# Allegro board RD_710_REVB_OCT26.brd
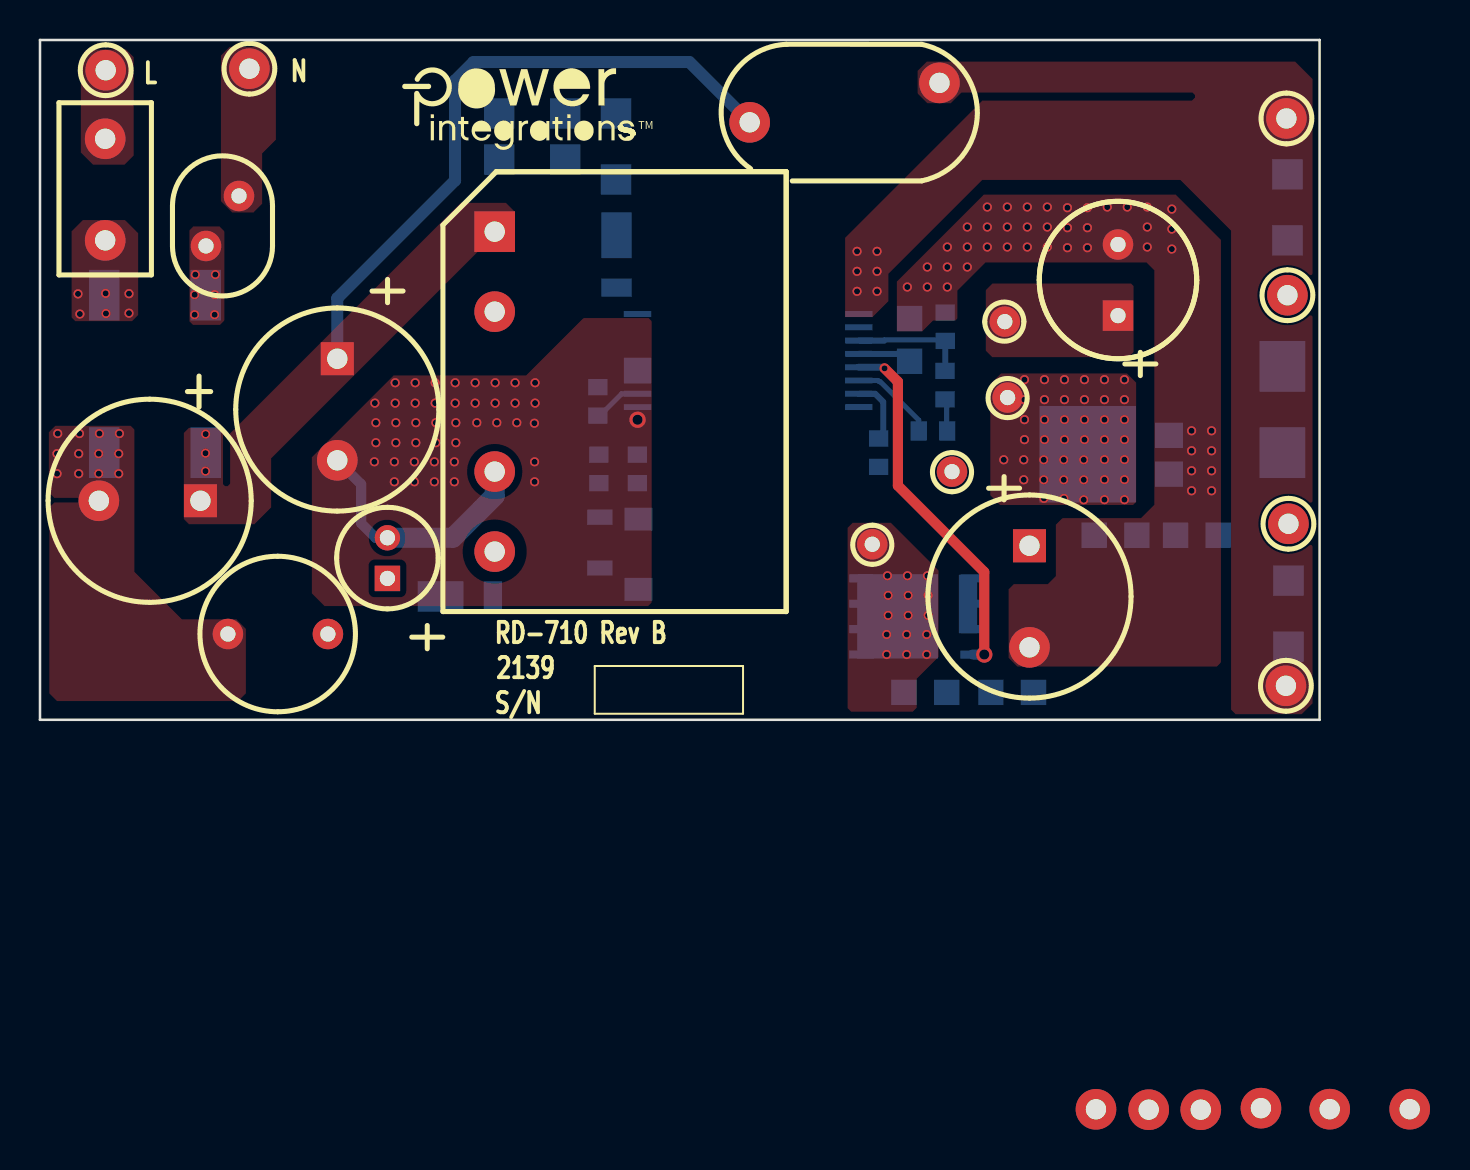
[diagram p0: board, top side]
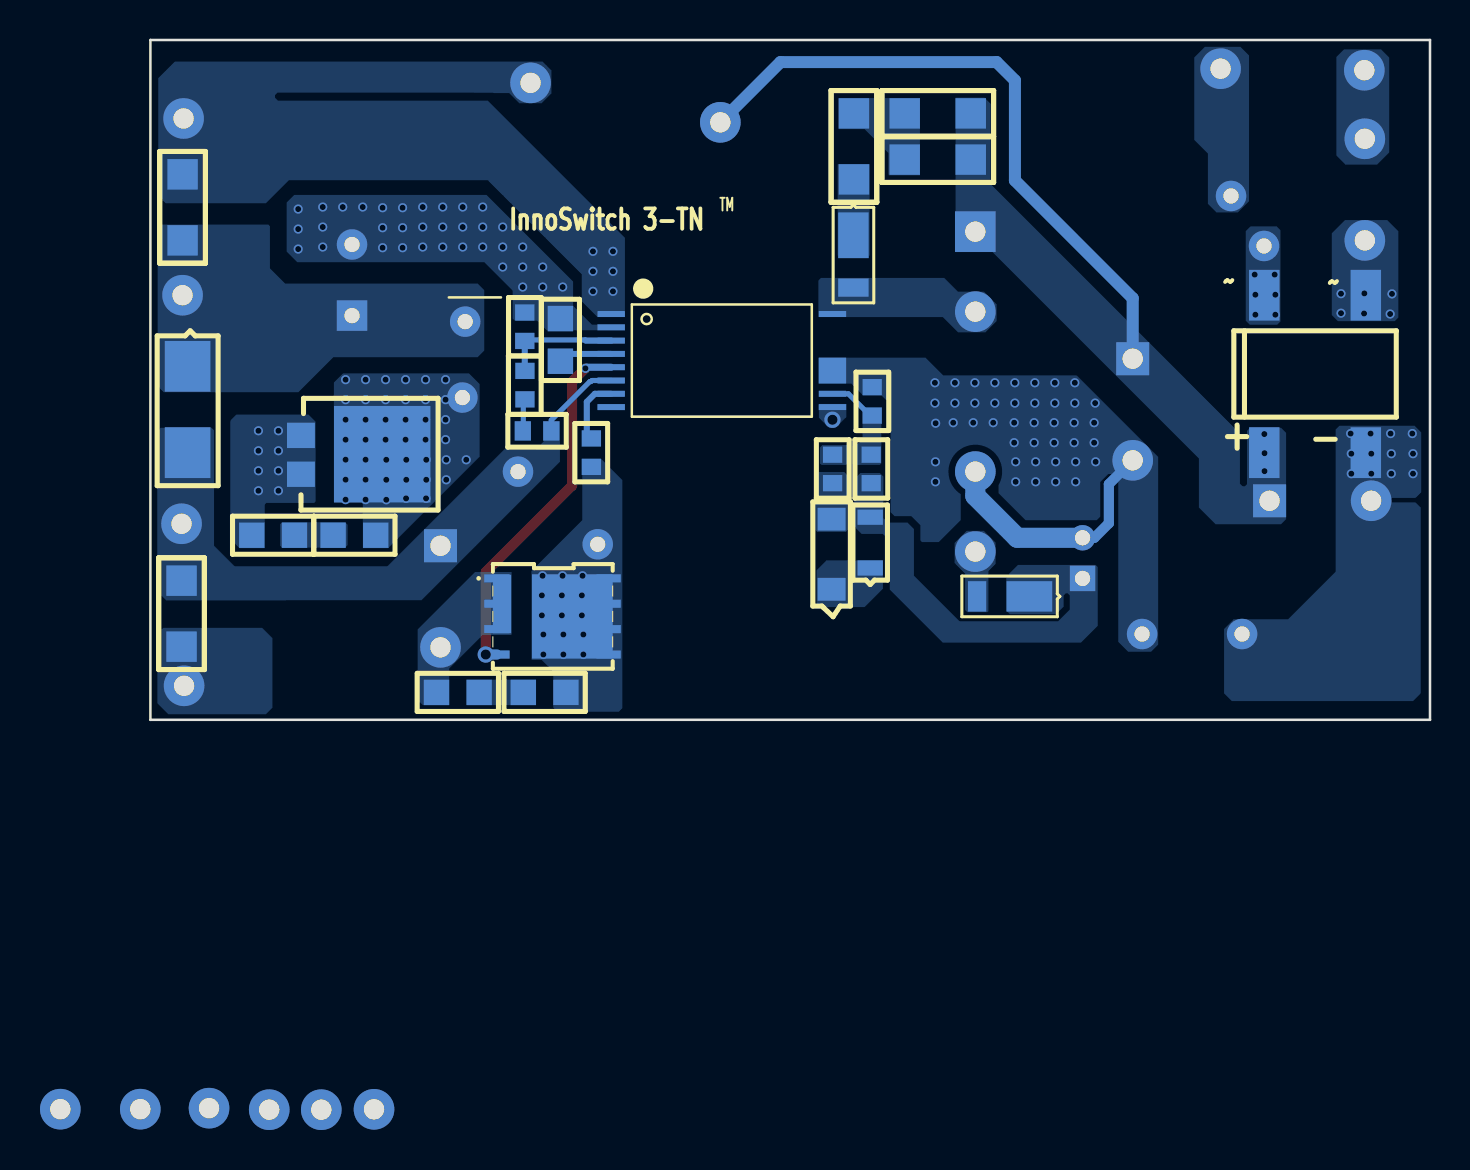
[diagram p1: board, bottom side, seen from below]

Outline 64 x 34 mm; copper layers: TOP, BOTTOM. Coordinates in mm from the lower left corner of the outline.
Outline path: 0,34 0,0 64,0 64,34 0,34

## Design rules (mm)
constraint set DEFAULT: min track width 0.508

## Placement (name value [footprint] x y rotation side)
BR1  DF08S  [PISMDDFS]  8.29 13.41 0 bottom
C1  15 uF  [PIPOLCAPCYLD400LS200040]  8.02 10.96 180 top
C2  15 uF  [PIPOLCAPCYLD400LS200040]  14.87 18.06 270 top
C3  1000 pF  [PISMC1206]  22.97 28.02 0 bottom
C4  22  uF  [PIPOLCAPCLYD200LS80030]  17.38 7.07 90 top
C5  0.47 uF  [PISMC0603]  27.9 15.21 90 bottom
C6  470 pF  [PINPCAPRAD8X5MMD030]  45.5 30.38 180 top
C7  2.2 uF  [PISMC0805]  43.49 20.07 270 bottom
C8  2.2 nF  [PISMC0805]  47.56 1.37 0 bottom
C9  1 nF  [PISMC0805]  52.73 9.23 0 bottom
C10  680 uF  [PIPOLCAPCYLD400LS200040]  49.49 8.71 270 top
C11  560 uF  [PIPOLCAPCLYD320LS140030]  53.92 20.22 90 top
C12  2.2 uF  [PISMC1206]  62.44 6.96 270 bottom
C13  2.2 uF  [PISMC1206]  62.39 23.98 90 bottom
C14  2.2 nF  [PISMC0603]  45.27 17.45 270 bottom
D1  DFLR1600-7  [PISMDDFLR120012]  28.84 24.26 90 bottom
D2  DFLR1200-7  [PISMDDFLR120012]  20.01 6.17 180 bottom
D3  BAV21WS-7-F  [PISMSOD323]  28 7.59 90 bottom
D4  V12P12-M3/86A  [PI_SM_D_TO-277A]  56.47 12.27 270 bottom
F1  1 A  [PI_RST_MICROFUSE]  3.26 29.06 270 top
FL1  Hole_30mils  [PI_HOLE_30MIL]  48.26 19.91 270 top
FL2  Hole_30mils  [PI_HOLE_30MIL]  48.4 16.12 0 top
FL3  Hole_30mils  [PI_HOLE_30MIL]  45.62 12.41 0 top
FL4  Hole_30mils  [PI_HOLE_30MIL]  41.63 8.78 0 top
L1  330 uH  [PICHOKETOKINVD345H453LS197D030]  9.4 4.29 0 top
LINE  WHT  [PITPKEYSTONE100X100]  10.47 32.56 0 top
NEUTRAL  BLK  [PITPKEYSTONE100X100]  3.29 32.49 0 top
NOREF  -  []  -227.6 -144.78 0 top
NOREF#2  -  []  64 34 270 top
NOREF#3  -  []  0 0 0 top
NOREF#4  -  []  -149.78 54.23 0 top
NOREF#5  -  []  18.2 32.38 0 top
Q1  SI7478DP-T1-E3  [PISMPQFN5X6B]  46.67 7.08 270 bottom
R1  200 k  [PISMR1206]  22.97 30.33 0 bottom
R2  68  [PISMR1206]  28.81 30.33 270 bottom
R3  36  [PISMR0603]  29.88 11.84 90 bottom
R4  12.7 k  [PISMR0603]  27.95 11.84 90 bottom
R5  47  [PISMR0603]  41.94 14.07 270 bottom
R7  62  [PISMR0805]  43.21 1.37 0 bottom
R8  30  [PISMR0805]  56.79 9.23 0 bottom
R9  100  [PISMR0603]  43.95 14.45 0 bottom
R10  3.0 Meg  [PISMR0603]  45.28 18.95 90 bottom
RT1  10  [PI_RAD_276DX197T_LS100D025]  9.13 23.7 90 top
T1  EE22  [PIBOBBINEE22V10PTDK]  22.74 24.41 0 top
U1  INN3074M  [PI_SM_MINSOP16A_1]  40.95 20.29 270 bottom
UNK5V  RED  [PITPKEYSTONE100X100]  62.44 9.8 0 top
UNK5VRTN  WHT  [PITPKEYSTONE100X100]  62.32 1.7 0 top
UNK12V  YEL  [PITPKEYSTONE100X100]  62.39 21.23 0 top
UNK12VRTN  BLK  [PITPKEYSTONE100X100]  62.34 30.07 0 top
VR1  MMSZ5234B-7-F  [PI_SM_SOD-123_12]  29.93 6.53 90 bottom
VR2  SMAZ8V2-13-F  [PISMDO214AC12]  62.14 17.68 270 bottom

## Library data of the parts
BR1 = DIODE BRIDGE_+-~~
C1 C2 = CAP POL: alternate symbols: (pipolcapclyd400x630ls200030h)
C3 C5-C9 C12-C14 = CAP NP
C4 = CAP POL: alternate symbols: (pipolcapclyd200ls80030h)
C10 = CAP POL: alternate symbols: (pipolcapclyd400x530ls200030h)
C11 = CAP POL: alternate symbols: (pipolcapclyd320ls140030430h)
D1-D3 = DIODE
D4 = DIODE SCHOTTKY_TO-277A
F1 = FUSE: alternate symbols: (pirstmicrofusehoz)
FL1-FL4 = FlyingLead
L1 = INDUCTOR
LINE UNK5V UNK5VRTN UNK12V UNK12VRTN = TESTPOINT
NEUTRAL = TESTPOINT: alternate symbols: (TP_TH_CR2_D1_1)
Q1 = FET_N_SGD_123_4_5678
R1-R5 R7-R10 = R
RT1 = THERMISTOR
T1 = BEEL22_10P/GENERIC
U1 = Inno3TNMinSOP16_0
VR1 VR2 = DIODE_ZENER

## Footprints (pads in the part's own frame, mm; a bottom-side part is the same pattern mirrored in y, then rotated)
PI_HOLE_30MIL
  round 1.524 hole 0.762: 1(0,0)
PI_RAD_276DX197T_LS100D025
  round 1.524 hole 0.762: 1(0,0.825) 2(2.5,-0.825)
PI_RST_MICROFUSE
  round 2.032 hole 1.016: 1(0,0) 2(5.08,0)
PI_SM_D_TO-277A
  rect 1.27x1.397 smd: 1(-0.015,0) 2(-1.956,0)
  rect 4.826x4.826 smd: 3(-1.016,4.064)
PI_SM_MINSOP16A_1
  rect 0.3x1.37 smd: 1(0,0) 2(0.665,0) 3(1.33,0) 4(1.995,0) 5(2.66,0) 6(3.325,0) 7(3.99,0) 8(4.655,0) 9(4.655,11.067) 10(3.99,11.067) 16(0,11.067)
  rect 1.292x1.37 smd: 11(2.829,11.067)
PI_SM_SOD-123_12
  rect 1.143x1.397 smd: 1(0,0) 2(3.505,0)
PIBOBBINEE22V10PTDK
  rect 2.032x2.032 hole 1.016: 1(0,0)
  round 2.032 hole 1.016: 2(0,-4) 3(30.074,-43.891) 4(0,-11.999) 5(0,-15.999) 6(45.764,-43.885) 7(41.764,-43.885) 8(38.325,-43.834) 9(35.315,-43.91) 10(32.711,-43.91)
PICHOKETOKINVD345H453LS197D030
  round 1.524 hole 0.762: 1(0,0) 2(5.001,0)
PINPCAPRAD8X5MMD030
  round 2.032 hole 1.016: 1(0.508,-1.473) 2(10,0.5)
PIPOLCAPCLYD200LS80030
  rect 1.27x1.27 hole 0.762: 1(0,0)
  round 1.27 hole 0.762: 2(2.032,0)
PIPOLCAPCLYD320LS140030
  rect 1.524x1.524 hole 0.762: 1(0,0)
  round 1.524 hole 0.762: 2(3.556,0)
PIPOLCAPCYLD400LS200040
  rect 1.651x1.651 hole 1.016: 1(0,0)
  round 2.032 hole 1.016: 2(5.08,0)
PISMC0603
  rect 0.813x0.965 smd: 1(0,0) 2(1.422,0)
PISMC0805
  rect 1.27x1.27 smd: 1(0,0) 2(2.134,0)
PISMC1206
  rect 1.524x1.524 smd: 1(0,0) 2(3.302,0)
PISMDDFLR120012
  rect 2.286x1.524 smd: 1(-0.025,0)
  rect 0.914x1.524 smd: 2(-2.642,0)
PISMDDFS
  rect 1.524x2.54 smd: 1(0,0.051) 2(-5.08,0.051) 3(0,-7.823) 4(-5.08,-7.823)
PISMDO214AC12
  rect 2.54x2.286 smd: 1(0,0) 2(4.318,0)
PISMPQFN5X6B
  rect 0.406x1.27 smd: 1(0,0) 2(1.27,0) 3(2.54,0) 4(3.81,0)
  rect 0.406x1.219 smd: 5(3.81,5.588) 6(2.54,5.588) 7(1.27,5.588) 8(0,5.588)
PISMR0603
  rect 0.813x0.965 smd: 1(0,0) 2(1.422,0)
PISMR0805
  rect 1.27x1.27 smd: 1(0,0) 2(2.134,0)
PISMR1206
  rect 1.524x1.524 smd: 1(0,0) 2(3.302,0)
PISMSOD323
  rect 0.762x1.27 smd: 1(0,0) 2(2.54,0)
PITPKEYSTONE100X100
  round 2.032 hole 1.016: 1(0,0)

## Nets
0: C2.2 C4.2 C5.2 L1.2 T1.4 U1.9 U1.11
N11170432: BR1.1 C1.1 C2.1 C3.1 C6.2 R1.1 T1.1
N11170440: C6.1 C12.2 C13.2 U1.1 UNK5VRTN.1 UNK12VRTN.1
N11170470: C11.1 C13.1 FL1.1 UNK12V.1 VR2.1
N11170588: C9.1 D4.3(CATHODE) FL2.1
N11170596: C9.2 R8.1
N11170600: C7.1 C8.2 C10.2 C11.2 D4.1 D4.2 Q1.1 Q1.2 Q1.3(S3) R8.2 R10.2 U1.2
N11170726: C10.1 C12.1 FL3.1 R9.1 U1.6 UNK5V.1 VR2.2
N11170802: D1.2 T1.2 U1.16
N11170962: C3.2 R1.2 R2.1
N11171012: BR1.2 C1.2 L1.1
N11171092: BR1.4 F1.2
N11171100: BR1.3 RT1.1
N11171108: FL4.1 Q1.5 Q1.6 Q1.7 Q1.8 R5.2 R7.1
N11171116: C8.1 R7.2
N11171166: D2.2 T1.5
N11171218: D1.1 R2.2
N11171358: Q1.4 U1.5
N11171410: F1.1 NEUTRAL.1
N11171438: LINE.1 RT1.2
N11171478: C14.1 R10.1 U1.3
N11171534: R5.1 U1.7
N11171542: C7.2 U1.4
N11171554: C14.2 R9.2
N11171566: C4.1 D2.1 D3.2 R4.1
N11171654: D3.1 VR1.1
N11171658: R3.1 VR1.2
N11171726: C5.1 R3.2 R4.2 U1.10

Pads without a net: T1 3 6 7 8 9 10; U1 8

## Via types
v1: diameter 0.457, hole 0.305, TOP to BOTTOM, 176 vias
v2: diameter 0.813, hole 0.508, TOP to BOTTOM, 2 vias

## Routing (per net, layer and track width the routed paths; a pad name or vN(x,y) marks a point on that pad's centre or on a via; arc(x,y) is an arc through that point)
0: length 12.7
  BOTTOM w0.508: C4.2 16.79,9.1 16.06,9.83 16.06,11.79 C2.2
  BOTTOM w1: T1.4 22.74,11.2 20.65,9.1 C4.2
  vias: v1(16.75,15.84) v1(16.72,12.9) v1(16.8,14.86) v1(16.8,13.86) v1(17.72,12.9) v1(17.72,11.9) v1(17.77,16.86) v1(17.77,15.84) v1(17.8,14.86) v1(17.8,13.86) v1(18.72,12.9) v1(18.72,11.9) v1(18.77,16.86) v1(18.77,15.84) v1(18.8,14.86) v1(18.8,13.86) v1(19.72,12.9) v1(19.72,11.9) v1(19.77,16.86) v1(19.77,15.84) v1(19.8,14.86) v1(19.8,13.86) v1(20.72,12.9) v1(20.72,11.9) v1(20.77,16.86) v1(20.77,15.84) v1(20.8,14.86) v1(20.8,13.86) v1(21.77,16.86) v1(21.77,15.84) v1(21.85,14.86) v1(22.77,16.86) v1(22.77,15.84) v1(22.85,14.86) v1(23.76,16.86) v1(23.76,15.84) v1(23.85,14.86) v1(24.73,14.83) v1(24.74,12.9) v1(24.74,11.9) v1(24.76,16.86) v1(24.76,15.84) v2(29.89,15.01)
N11170432: length 32.7
  BOTTOM w0.6: C6.2 32.48,32.89 21.68,32.89 20.76,31.98 20.76,26.97 14.87,21.08 C2.1
  vias: v1(8.29,14.29) v1(8.28,13.34) v1(8.28,12.44)
N11170440:
  vias: v1(40.87,23.43) v1(40.87,22.43) v1(40.87,21.43) v1(41.87,23.43) v1(41.87,22.43) v1(41.87,21.43)
N11170588:
  vias: v1(48.2,13) v1(49.24,17.01) v1(49.24,16.01) v1(49.24,15.01) v1(49.24,14.01) v1(49.2,13) v1(49.2,12) v1(50.24,17.01) v1(50.24,16.01) v1(50.24,15.01) v1(50.24,14.01) v1(50.2,13) v1(50.2,12) v1(50.21,11.07) v1(51.24,17.01) v1(51.24,16.01) v1(51.24,15.01) v1(51.24,14.01) v1(51.2,13) v1(51.2,12) v1(51.21,11.07) v1(52.24,17.01) v1(52.24,16.01) v1(52.24,15.01) v1(52.24,14.01) v1(52.2,13) v1(52.2,12) v1(52.2,11) v1(53.24,17.01) v1(53.24,16.01) v1(53.24,15.01) v1(53.24,14.01) v1(53.24,13.01) v1(53.24,12.01) v1(53.24,11.01) v1(54.24,17.01) v1(54.24,16.01) v1(54.24,15.01) v1(54.24,14.01) v1(54.24,13.01) v1(54.24,12.01) v1(54.24,11.01)
N11170600:
  vias: v1(43.38,21.64) v1(44.38,22.64) v1(44.38,21.64) v1(45.38,23.64) v1(45.38,22.64) v1(45.38,21.64) v1(46.38,24.64) v1(46.38,23.64) v1(46.38,22.64) v1(47.38,25.64) v1(47.38,24.64) v1(47.38,23.64) v1(48.38,25.64) v1(48.38,24.64) v1(48.38,23.64) v1(49.38,25.64) v1(49.38,24.64) v1(49.38,23.64) v1(50.38,25.64) v1(50.38,24.64) v1(50.38,23.64) v1(51.39,25.61) v1(51.39,24.61) v1(51.39,23.61) v1(52.39,25.61) v1(52.39,24.61) v1(52.39,23.61) v1(53.38,25.64) v1(54.38,25.64) v1(55.38,25.64) v1(55.38,24.64) v1(55.38,23.64) v1(56.61,25.54) v1(56.61,24.54) v1(56.61,23.54) v1(57.6,14.46) v1(57.6,13.46) v1(57.6,12.46) v1(57.6,11.46) v1(58.6,14.46) v1(58.6,13.46) v1(58.6,12.46) v1(58.6,11.46)
N11170726: length 4.4
  BOTTOM w0.254: U1.6 41.92,16.97 41.97,16.92 42.02,16.92 43.95,14.99 R9.1
N11171012:
  vias: v1(0.89,14.32) v1(0.85,13.31) v1(0.85,12.31) v1(1.94,13.31) v1(1.94,12.31) v1(1.97,14.32) v1(2.94,13.31) v1(2.94,12.31) v1(2.97,14.32) v1(3.94,13.31) v1(3.94,12.31) v1(3.97,14.32)
N11171092:
  vias: v1(1.9,21.3) v1(1.99,20.29) v1(3.28,21.33) v1(3.3,20.32) v1(4.45,21.31) v1(4.45,20.34)
N11171100:
  vias: v1(7.73,21.26) v1(7.73,20.26) v1(7.77,22.27) v1(8.73,21.26) v1(8.73,20.26) v1(8.77,22.27)
N11171108:
  vias: v1(42.35,4.27) v1(42.35,3.27) v1(42.39,7.2) v1(42.42,6.22) v1(42.42,5.22) v1(43.35,4.27) v1(43.35,3.27) v1(43.39,7.2) v1(43.42,6.22) v1(43.42,5.22) v1(44.35,4.27) v1(44.35,3.27) v1(44.39,7.2) v1(44.42,6.22) v1(44.42,5.22)
N11171358: length 18.2
  TOP w0.508: v2(47.23,3.27) 47.23,7.39 42.91,11.71 42.91,16.91 v1(42.24,17.58)
  BOTTOM w0.35: U1.5 42.17,17.63 42.23,17.58 v1(42.24,17.58)
  BOTTOM w0.508: Q1.4 v2(47.23,3.27)
N11171478: length 5.9
  BOTTOM w0.254: R10.1 45.23,19 42.26,19 42.22,18.96
  BOTTOM w0.3: R10.1 45.28,17.46 C14.1
  BOTTOM w0.305: U1.3 42.22,18.96
N11171534: length 3.3
  BOTTOM w0.3: U1.7 41.77,16.3 42.17,15.9 42.17,14.3 R5.1
N11171542: length 2.7
  BOTTOM w0.3: C7.2 43.13,18.3 U1.4
N11171554: length 1.6
  BOTTOM w0.254: R9.2 45.35,14.47 45.35,15.95 C14.2
N11171726: length 2.4
  BOTTOM w0.254: U1.10 29.09,16.3 28,15.21 C5.1

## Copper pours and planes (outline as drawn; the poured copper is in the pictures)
0 on TOP: 30.59,5.87 30.41,5.69 14.23,5.69 13.6,6.32 13.6,13.13 17.69,17.22 24.32,17.22 27.19,20.09 30.44,20.09 30.59,19.94 ; 2 cut-outs
0 on BOTTOM: 25.23,18.11 30.57,18.11 30.59,18.08 30.59,16.84 30.57,16.81 28.94,16.81 28.36,16.23 27.44,16.23 26.98,15.77 26.98,10.39 26.78,10.19 25.94,10.19 25.49,9.73 25.49,8.97 25.41,8.89 24.57,8.89 23.47,9.99 23.47,11.28 23.92,11.77 24.09,12.41 22.74,13.76 21.4,12.41 21.45,12.06 21.58,11.74 21.58,11.34 20.23,9.98 16.67,9.98 16.49,10.16 16.49,11.89 16.09,12.29 15.83,12.29 15.59,12.05 15.59,3.9 15.1,3.4 13.95,3.4 13.6,3.76 13.6,13.16 17.66,17.22 24.34,17.22
0 on BOTTOM: 29.19,15.8 29.19,15.14 29.73,14.61 30.06,14.61 30.57,15.11 30.57,15.8
N11170432 on TOP: 21.88,23.39 23.73,23.39 23.73,25.42 23.3,25.85 21.05,25.85 20.62,25.42 20.61,25.43 9.51,14.33 9.51,11.81 9.38,11.68 9.26,11.68 9.15,11.79 9.15,14.45 9,14.61 7.45,14.61 7.2,14.35 7.2,10.03 7.45,9.78 10.72,9.78 11.56,10.62 11.56,13.07
N11170432 on BOTTOM: 21.88,23.39 23.73,23.39 23.73,31.11 22.29,31.11 21.98,30.81 21.98,26.8 9.51,14.33 9.51,11.81 9.38,11.68 9.26,11.68 9.15,11.79 9.15,14.45 9,14.61 7.45,14.61 7.2,14.35 7.2,10.03 7.45,9.78 10.72,9.78 11.56,10.62 11.56,13.07
N11170440 on TOP: 63.65,32.04 63.65,22.05 63.11,22.55 62.39,22.73 60.89,21.23 62.39,19.73 63.11,19.92 63.65,20.42 63.65,10.7 63.12,11.14 62.44,11.3 60.94,9.8 62.44,8.3 63.12,8.47 63.65,8.91 63.65,0.83 63.1,0.28 59.8,0.28 59.57,0.51 59.57,24.46 57.03,27 47.13,27 42.43,22.3 42.43,20.93 41.64,20.14 40.27,20.14 40.27,24.1 47.13,30.96 57.62,30.96 57.77,31.11 57.77,31.24 57.64,31.37 46.09,31.37 45.55,30.84 44.38,30.84 43.9,31.32 43.9,32.46 44.36,32.92 62.77,32.92
N11170440 on BOTTOM: 57.9,0.61 58.23,0.28 63.1,0.28 63.65,0.83 63.65,4.31 63.36,4.6 58.4,4.6 57.9,4.09
N11170440 on BOTTOM: 63.61,32.08 63.61,26.21 63.23,25.83 58.23,25.83 57.07,26.99 47.13,26.99 42.43,22.29 42.43,20.93 41.64,20.14 40.27,20.14 40.27,24.1 47.13,30.96 57.62,30.96 57.77,31.11 57.77,31.24 57.64,31.37 47.81,31.37 47.8,31.36 46.83,31.36 46.82,31.34 46.06,31.34 45.55,30.84 44.43,30.84 43.94,31.33 43.94,32.47 44.38,32.92 62.77,32.92
N11170470 on TOP: 47.63,21.82 54.57,21.82 54.7,21.69 54.7,18.39 54.44,18.14 47.63,18.14 47.3,18.47 47.3,21.49
N11170470 on BOTTOM: 47.63,18.14 54.85,18.14 56.6,16.38 63.33,16.38 63.64,16.69 63.64,24.59 63.46,24.77 58.1,24.77 58.02,24.69 58.02,22.58 57.26,21.82 47.63,21.82 47.3,21.49 47.3,18.47
N11170588 on TOP: 54.82,10.9 54.82,16.87 54.37,17.32 48.07,17.32 47.53,16.79 47.53,11.23 48.02,10.74 54.67,10.74
N11170588 on BOTTOM: 54.82,10.92 54.77,10.87 53.45,10.87 53.37,10.79 53.37,8.59 52.1,8.59 47.53,13.16 47.53,16.79 48.07,17.32 54.37,17.32 54.82,16.87
N11170596 on BOTTOM: 54.26,9.88 57.41,9.88 57.52,9.78 57.52,8.71 57.41,8.61 54.26,8.61 54.14,8.74 54.14,9.75
N11170600 on BOTTOM (solid shape): 46.87,4.33 45.96,4.33 45.96,7.25 46.87,7.25
N11170600 on TOP: 55.06,10.08 51.14,10.08 50.81,9.75 50.81,7.19 50.4,6.78 48.7,6.78 48.45,6.53 48.45,3.1 48.88,2.67 58.86,2.67 59.06,2.87 59.06,24 56.8,26.26 47.2,26.26 42.86,21.92 42.86,19.43 44.13,19.43 44.66,19.96 45.78,19.96 45.88,20.07 45.88,21.46 47.29,22.87 55.34,22.87 55.74,22.48 55.74,10.76
N11170600 on BOTTOM: 47.19,26.25 56.8,26.25 57.18,25.87 57.18,23.42 56.65,22.89 47.3,22.89 45.88,21.46 45.88,20.07 45.78,19.96 44.66,19.96 44.18,19.48 40.27,19.48 40.27,19.76 41.92,19.76 42.86,20.7 42.86,21.92
N11170600 on BOTTOM: 47.76,7.39 45.93,7.39 45.93,4.27 45.96,4.24 47.38,4.24 49.06,2.57 49.06,0.74 50.38,0.74 50.63,0.99 50.63,4.52
N11170600 on BOTTOM: 58.28,10.77 58.28,8.59 59.55,8.59 60,9.04 60,14.93 59.99,14.94 59.99,14.97 59.7,15.27 56.09,15.27 55.74,14.91 55.74,10.92 55.81,10.85 58.2,10.85
N11170726 on BOTTOM: 60.94,14.61 63.48,14.61 63.66,14.43 63.66,6.43 63.2,5.97 57.24,5.97 57.22,5.98 50.44,5.98 43.52,12.9 43.52,14.94 44.33,14.94 44.33,13.92 44.71,13.54 46.29,13.54 52.14,7.68 59.79,7.68 60.82,8.71 60.82,14.48
N11170802 on BOTTOM: 30.46,22.1 30.59,21.97 30.59,20.17 30.57,20.14 24.37,20.14 23.61,19.38 22.23,19.38 21.68,19.94 21.68,20.78 22.31,21.41 23.61,21.41 24.29,22.1
N11170962 on BOTTOM: 25.51,27.23 25.51,31.09 29.57,31.09 29.57,29.54 28.28,29.54 27.09,28.35 27.09,27.25 27.06,27.23
N11171012 on TOP, BOTTOM: 7.1,5.03 9.84,5.03 9.84,5 10.3,4.55 10.3,1.32 9.92,0.94 0.85,0.94 0.47,1.32 0.47,10.62 0.72,10.87 1.91,10.87 1.97,10.92 1.97,11.02 1.89,11.1 0.72,11.1 0.44,11.38 0.44,14.38 0.77,14.71 4.53,14.71 4.72,14.52 4.72,7.4
N11171092 on TOP, BOTTOM: 4.61,19.94 4.91,20.24 4.91,24.33 4.25,24.99 2.14,24.99 1.58,24.43 1.58,20.12 1.76,19.94
N11171100 on TOP, BOTTOM: 7.65,19.75 7.48,19.93 7.48,24.49 7.67,24.68 8.98,24.68 9.22,24.43 9.22,19.96 9.01,19.75
N11171108 on BOTTOM (solid shape): 44.92,3.06 40.88,3.06 40.88,7.28 44.92,7.28
N11171108 on TOP: 40.4,0.58 40.57,0.41 43.65,0.41 43.85,0.61 43.85,2.06 44.94,3.15 44.94,7.47 42.55,9.86 40.65,9.86 40.4,9.6
N11171108 on BOTTOM: 40.4,0.58 40.57,0.41 43.65,0.41 43.85,0.61 43.85,2.41 44.43,3 44.92,3 44.94,3.02 44.94,7.44 42.4,9.98 42.4,13.06 41.46,13.06 40.4,11.99
N11171116 on BOTTOM: 44.71,2.01 44.71,0.74 48.17,0.74 48.17,2.01
N11171166 on BOTTOM: 21.73,7.8 21.73,8.86 22.31,9.45 23.17,9.45 23.78,8.84 23.78,7.85 23.25,7.32 23.25,5.49 23.15,5.38 22.13,5.38 22.08,5.44 22.08,7.44
N11171218 on BOTTOM: 28.03,27.79 28.03,23.22 29.63,23.22 29.63,27.79
N11171410 on TOP, BOTTOM: 2.65,27.76 4.23,27.76 4.68,28.22 4.68,33.15 4.3,33.53 2.45,33.53 2.04,33.12 2.04,28.37
N11171438 on TOP, BOTTOM: 11.79,29.01 11.79,33.12 11.26,33.66 9.48,33.66 9.05,33.22 9.05,25.93 9.61,25.37 10.68,25.37 11.11,25.81 11.11,28.32
N11171566 on BOTTOM: 21.19,7.16 20.61,7.75 16.72,7.75 16.62,7.65 16.62,4.7 17.46,3.86 24.37,3.86 27.02,6.52 27.02,8.95 27.37,9.3 28.43,9.3 28.79,9.65 28.79,12.04 28.48,12.34 27.52,12.34 27.34,12.17 27.34,10.08 27.12,9.87 26.13,9.87 25.82,9.55 25.82,7.21 23.53,4.93 18.6,4.93 18.02,5.51 18.02,6.22 18.12,6.32 18.22,6.32 18.32,6.22 18.32,5.66 18.7,5.28 21.02,5.28 21.19,5.46
N11171654 on BOTTOM: 30.18,7.98 30.68,7.48 30.68,5.75 30.57,5.64 28.28,5.64 27.37,6.55 27.37,7.98
N11171658 on BOTTOM: 29.3,12.4 30.62,12.4 30.77,12.24 30.77,9.53 30.64,9.4 29.22,9.4 29.12,9.5 29.12,12.22
N11171726 on BOTTOM: 28.38,14.05 28.38,15.6 28.36,15.62 27.44,15.62 27.44,12.83 27.52,12.75 30.44,12.75 30.51,12.83 30.51,13.61 30.39,13.74 28.69,13.74

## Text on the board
Ref Des/Silkscreen Bottom: TM | InnoSwitch 3-TN
Ref Des/Silkscreen Top: L | N | RD-710 Rev B | S/N | 2139
User.5: 14.  FAB HOUSE LOGO,DATE CODE TO BE IN SILK SCREEN ONLY.DO NOT USE COPPER. | 13.  MATERIAL FR4 COPPER 2oz THICKNESS 0.062" | FL1,FL2,FL3 and FL4 ARE FLYING LEAD FROM T1 | PLEASE DELETE THESE PINS
User.8: FIGURE | FINISHED_SIZE | 0.3048 | 0.508 | 0.762 | 1.016 | DRILL CHART: TOP to BOTTOM | ALL UNITS ARE IN MILLIMETERS | TOLERANCE_DRILL | +0.0762/-0.0762 | PLATED | QTY | 176 | 2 | 12 | 10 | 16
